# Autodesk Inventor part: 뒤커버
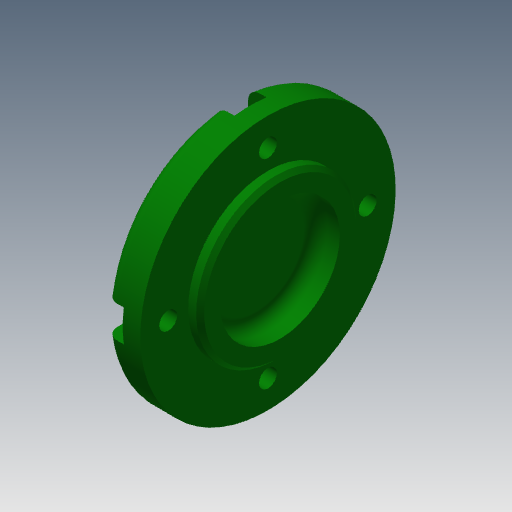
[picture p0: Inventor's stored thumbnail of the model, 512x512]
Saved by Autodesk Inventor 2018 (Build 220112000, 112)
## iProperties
Created: 2019-01
Part Number: 뒤커버
Material: 알루미늄 6061
Document SubType Name: Modeling
Designer: mduedu
Density: 2.71 g/cm^3
Appearance: 진녹색
Mass: 71.8559 g
Surface Area: 92.0216 cm^2
Volume: 26.5151 cm^3
Author: mduedu
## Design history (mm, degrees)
sketch "스케치1"
  geometry: L1 (0, 0)-(9, 0); L2 (9, 0)-(9, 32); L3 (9, 32)-(0, 32); L4 (0, 32)-(0, 0); L5 (9, 0)-(12, 0); L6 (12, 0)-(12, 20); L7 (12, 20)-(9, 20); L8 (9, 20)-(9, 0)
  constraints: 16 end point, 4 parallel, 2 horizontal, 2 perpendicular
  dimensions: "d0" = 12 distance between parallel lines of L6 L4; "d2" = 64 diameter of L3 L1; "d3" = 40 diameter of L7 L5; "d4" = 3 distance between parallel lines of L6 L2
revolve "회전1" sketch "스케치1" stored, may be unused: angle "d5" = 90 deg
sketch "스케치4"
  geometry: C1 r 15 at (0, 0); 1 further point
  constraints: 1 centre point, 1 coincident
  dimensions: "d24" = 30 diameter of C1
extrude "돌출1" cut sketch "스케치4" distance "d25" = 6; taper "d26" = 0 deg
fillet "모깎기4" dims "d27" = 3
fillet "모깎기3" dims "d18" = 3
chamfer "모따기2" distance "d28" = 1; stored, may be unused: second distance "d29" = 2, angle "d30" = 45 deg
sketch "스케치3" dims "d19" = 50
  geometry: 6 further points
  constraints: 2 vertical alignment, 1 coincident, 7 other
  dimensions: "d22" = 360 deg dimension on point (0, 0) point (0, 25) (derived)
sketch "스케치5"
  geometry: 4 further points
  constraints: 4 other
hole "구멍1" sketch "스케치5" at (-25, 0), (0, -25), (25, 0), (0, 25) diameter "d31" = 4.5; stored, may be unused: countersink angle "d35" = 90 deg, drill point angle "d37" = 0 deg; dims "d32" = 6, "d33" = 8, "d34" = 4.6, "d36" = 8
sketch "스케치6"
  geometry: L1 (-4, 0)-(-4, 6.749); L2 (4, 0)-(4, 6.749); A1 r 4 centre (0, 0) between (0, 4) and (-4, 0) reference; A2 r 32 centre (0, -25) between (-4, 6.749) and (4, 6.749) reference; A3 r 4 centre (0, 0) between (-4, 0) and (4, 0); A4 r 32 centre (0, -25) between (4, 6.749) and (-4, 6.749); A5 r 4 centre (0, 0) between (4, 0) and (-4, 0); 1 further point
  constraints: 10 point on circle, 4 end point, 3 centre point, 2 coincident, 2 tangent, 1 parallel, 1 vertical
extrude "돌출2" cut sketch "스케치6" extent not by distance; stored distance "d38" = 10; taper "d39" = 0 deg
node "솔리드1"
pattern_circular "원형 패턴1" dims angle "d41" = 360 deg
